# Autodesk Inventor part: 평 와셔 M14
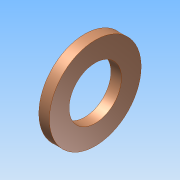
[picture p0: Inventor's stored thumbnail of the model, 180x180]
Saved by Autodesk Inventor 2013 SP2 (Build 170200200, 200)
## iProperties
Created: 2025-08
Part Number: 평 와셔 M14
Material: Generic
Document SubType Name: Modeling
Designer: i
Density: 1 g/cm^3
Author: i
변환 표준: STEP AP214IS
전처리기: Build: 200, Release: 2013 SP2 Update 6 - Date: Thu 07/17/2014
전송 단위: 밀리미터
불확실성: 0.01
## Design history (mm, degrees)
node "평 와셔 M141"
body "Solid1"
node "기준1"
